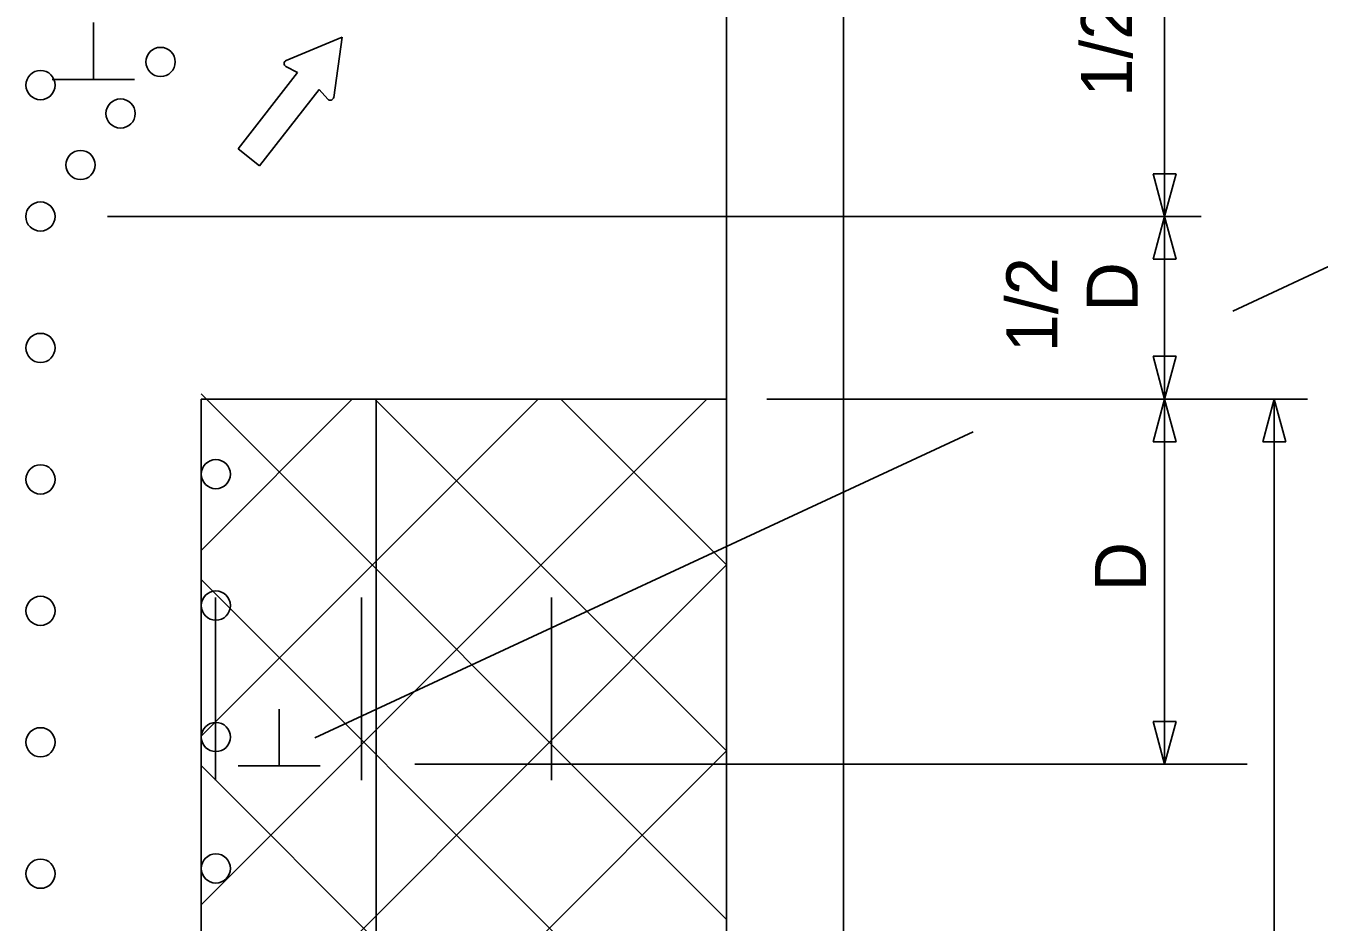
# Model space of a CAD drawing. Extents: x 16738 to 19504, y 5697 to 6916.
# Drawn here: x 16987.4 to 17164.6, y 6410.3 to 6533.1 of the extents above; entities that cross this region are included whole.
import ezdxf

# ---------------------------------------------------------------- set-up
doc = ezdxf.new("R2010")
doc.units = 0
for name, color, linetype in [('ALI_LEGAL_EX', 7, 'Continuous'), ('MT_SCRATCH_LEVEL_A', 7, 'Continuous'), ('MT_SCRATCH_LEVEL_E', 7, 'Continuous'), ('PAVT_EDGE_EX', 7, 'Continuous'), ('TRAFFIC_SIGNS_PR', 7, 'Continuous'), ('TYPICAL_TEXT_DIMEN_PR', 7, 'Continuous')]:
    doc.layers.add(name, color=color, linetype=linetype)

msp = doc.modelspace()

# ---------------------------------------------------------------- linework, layer by layer
at = {"layer": 'ALI_LEGAL_EX'}
for points in [[(17013.43, 6454.77), (17013.43, 6429.77)], [(17033.43, 6454.77), (17033.43, 6429.77)], [(17059.43, 6454.77), (17059.43, 6429.77)]]:
    msp.add_lwpolyline(points, dxfattribs=at)
at = {"layer": 'MT_SCRATCH_LEVEL_A'}
for p, q in [((17083.43, 6410.69), (17011.43, 6482.69)), ((17011.43, 6481.95), (17083.43, 6481.95)), ((17083.43, 6481.95), (17011.43, 6481.95)), ((17011.43, 6412.69), (17080.7, 6481.95)), ((17011.43, 6461.23), (17032.15, 6481.95)), ((17011.43, 6435.78), (17057.61, 6481.95)), ((17083.43, 6433.78), (17035.26, 6481.95)), ((17083.43, 6459.23), (17060.72, 6481.95)), ((17011.43, 6387.23), (17083.43, 6459.23)), ((17083.43, 6385.24), (17011.43, 6457.24)), ((17083.43, 6445.95), (17083.43, 6329.72)), ((17083.43, 6361.78), (17083.43, 6445.95)), ((17011.43, 6361.78), (17083.43, 6433.78)), ((17081.44, 6361.78), (17011.43, 6431.78))]:
    msp.add_line(p, q, dxfattribs=at)
at = {"layer": 'MT_SCRATCH_LEVEL_E'}
for p, q in [((17030.78, 6531.53), (17023.09, 6528.34)), ((17030.78, 6531.53), (17023.09, 6528.34)), ((17029.61, 6523.27), (17030.78, 6531.53)), ((17029.61, 6523.27), (17030.78, 6531.53)), ((17024.64, 6526.66), (17016.51, 6516.2)), ((17024.64, 6526.66), (17016.51, 6516.2)), ((17023.05, 6527.5), (17024.64, 6526.66)), ((17023.05, 6527.5), (17024.64, 6526.66)), ((17019.46, 6513.9), (17027.6, 6524.36)), ((17019.46, 6513.9), (17027.6, 6524.36)), ((17027.6, 6524.36), (17028.81, 6523.03)), ((17027.6, 6524.36), (17028.81, 6523.03)), ((17016.51, 6516.2), (17019.46, 6513.9)), ((17016.51, 6516.2), (17019.46, 6513.9))]:
    msp.add_line(p, q, dxfattribs=at)
for centre, start, end in [((17023.27, 6527.91), 112.5589, 242.0978), ((17023.27, 6527.91), 112.5589, 242.0978), ((17029.15, 6523.35), 222.1702, 351.9071), ((17029.15, 6523.35), 222.1702, 351.9071)]:
    msp.add_arc(centre, 0.463, start, end, dxfattribs=at)
at = {"layer": 'PAVT_EDGE_EX'}
for p, q in [((17083.43, 6911.29), (17083.43, 6113.54)), ((17099.43, 6911.29), (17099.43, 6113.54)), ((17011.43, 6481.95), (17011.43, 6329.72)), ((17035.43, 6481.95), (17035.43, 6299.46))]:
    msp.add_line(p, q, dxfattribs=at)
at = {"layer": 'TRAFFIC_SIGNS_PR'}
for centre in [(17005.89, 6528.12), (16989.44, 6524.95), (17000.41, 6521.06), (16994.92, 6514.01), (16989.43, 6506.95), (16989.44, 6488.95), (17013.46, 6471.67), (16989.44, 6470.95), (16989.44, 6452.95), (17013.46, 6453.67), (16989.44, 6434.95), (17013.46, 6435.67), (16989.44, 6416.95), (17013.46, 6417.67)]:
    msp.add_circle(centre, 2, dxfattribs=at)
at = {"layer": 'TYPICAL_TEXT_DIMEN_PR'}
for p, q in [((17143.43, 6506.95), (17143.43, 6565.4)), ((16996.69, 6525.74), (16996.69, 6533.52)), ((17002.31, 6525.74), (16991.06, 6525.74)), ((17143.43, 6506.95), (17141.86, 6512.81)), ((17141.86, 6512.81), (17143.43, 6512.81)), ((17143.43, 6512.81), (17145, 6512.81)), ((17145, 6512.81), (17143.43, 6506.95)), ((17148.43, 6506.95), (16998.6, 6506.95)), ((17141.86, 6501.09), (17143.43, 6506.95)), ((17143.43, 6506.95), (17145, 6501.09)), ((17143.43, 6506.95), (17143.43, 6481.95)), ((17178.79, 6506.12), (17152.76, 6494.01)), ((17143.43, 6501.09), (17141.86, 6501.09)), ((17145, 6501.09), (17143.43, 6501.09)), ((17143.43, 6481.95), (17141.86, 6487.81)), ((17141.86, 6487.81), (17143.43, 6487.81)), ((17143.43, 6487.81), (17145, 6487.81)), ((17145, 6487.81), (17143.43, 6481.95)), ((17143.43, 6431.95), (17143.43, 6482.6)), ((17163.01, 6481.95), (17088.94, 6481.95)), ((17141.86, 6476.09), (17143.43, 6481.95)), ((17143.43, 6481.95), (17145, 6476.09)), ((17156.86, 6476.09), (17158.43, 6481.95)), ((17158.43, 6361.78), (17158.43, 6481.95)), ((17158.43, 6481.95), (17160.01, 6476.09)), ((17117.2, 6477.48), (17027.04, 6435.55)), ((17143.43, 6476.09), (17141.86, 6476.09)), ((17145, 6476.09), (17143.43, 6476.09)), ((17158.43, 6476.09), (17156.86, 6476.09)), ((17160.01, 6476.09), (17158.43, 6476.09)), ((17022.13, 6431.72), (17022.13, 6439.5)), ((17143.43, 6431.95), (17141.86, 6437.81)), ((17141.86, 6437.81), (17143.43, 6437.81)), ((17143.43, 6437.81), (17145.01, 6437.81)), ((17145.01, 6437.81), (17143.43, 6431.95)), ((17027.76, 6431.72), (17016.51, 6431.72)), ((17154.74, 6431.95), (17040.71, 6431.95))]:
    msp.add_line(p, q, dxfattribs=at)

# ---------------------------------------------------------------- texts
for s, p in [('1/2 L', (17138.98, 6523.36)), ('1/2', (17128.75, 6488.37)), ('D', (17139.75, 6493.94)), ('D', (17140.88, 6455.61))]:
    msp.add_text(s, height=7, rotation=90, dxfattribs=at).set_placement(p)

doc.saveas('drawing.dxf')
